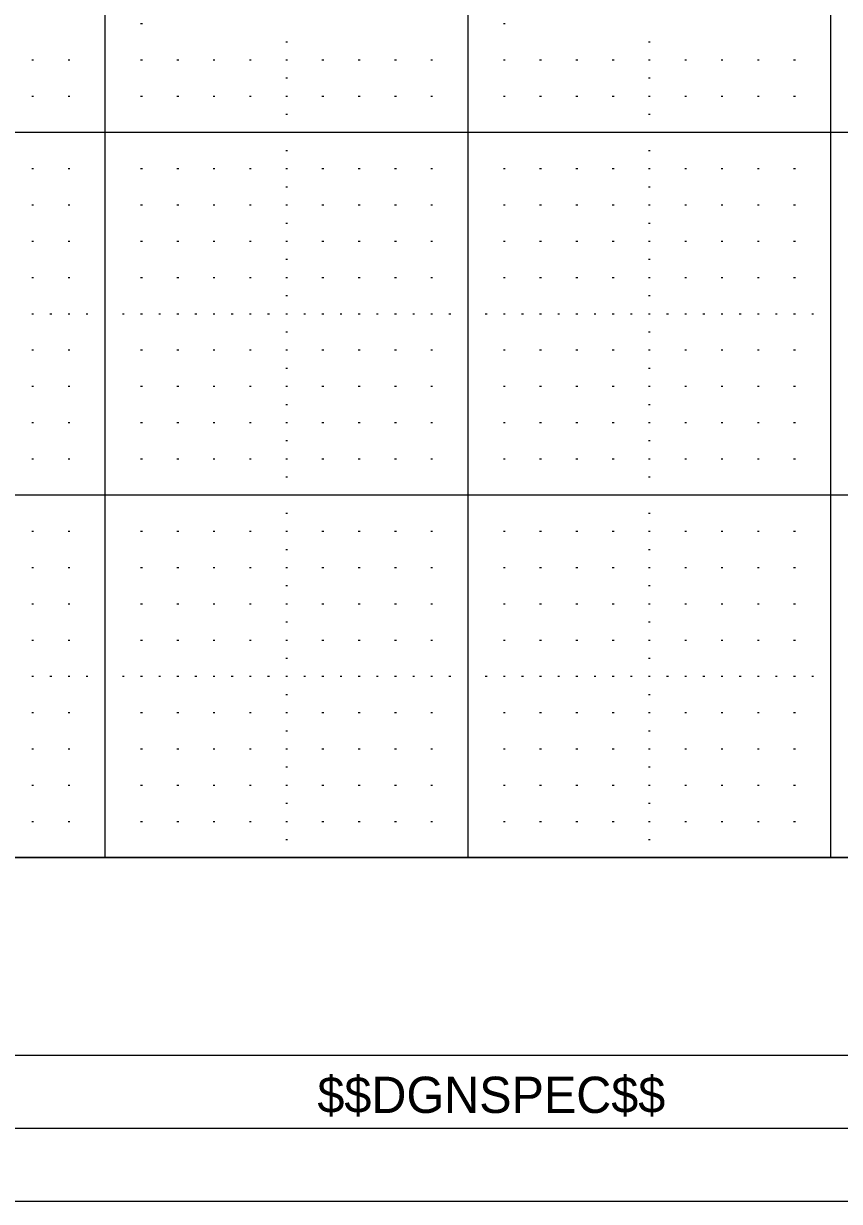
# Model space of a CAD drawing. Extents: x -3.6 to 32.1, y -0.4 to 25.6.
# Drawn here: x 27.583 to 29.832, y -0.403 to 2.845 of the extents above; entities that cross this region are included whole.
import ezdxf

# ---------------------------------------------------------------- set-up
doc = ezdxf.new("R2010")
doc.units = 0
for name, color, linetype in [('Level 4', 7, 'Continuous'), ('Level 48', 7, 'Continuous'), ('Level 5', 7, 'Continuous'), ('Level 62', 7, 'Continuous'), ('Level 63', 7, 'Continuous'), ('Level 63 Full', 7, 'Continuous'), ('R_Border Prem', 7, 'Continuous')]:
    doc.layers.add(name, color=color, linetype=linetype)

msp = doc.modelspace()

# ---------------------------------------------------------------- linework, layer by layer
at = {"layer": 'Level 4'}
for p, q in [((27.808, 0.545), (27.808, 19.545)), ((28.808, 0.545), (28.808, 19.545)), ((29.808, 0.545), (29.808, 19.545)), ((31.617, 2.545), (-0.001, 2.545)), ((31.617, 1.545), (-0.001, 1.545)), ((31.617, 0.545), (-0.001, 0.545))]:
    msp.add_line(p, q, dxfattribs=at)
at = {"layer": 'Level 5'}
for p, q in [((27.9055, 2.845), (27.9105, 2.845)), ((28.9055, 2.845), (28.9105, 2.845)), ((28.3055, 2.795), (28.3105, 2.795)), ((29.3055, 2.795), (29.3105, 2.795)), ((27.6055, 2.745), (27.6105, 2.745)), ((27.7055, 2.745), (27.7105, 2.745)), ((27.9055, 2.745), (27.9105, 2.745)), ((28.0055, 2.745), (28.0105, 2.745)), ((28.1055, 2.745), (28.1105, 2.745)), ((28.2055, 2.745), (28.2105, 2.745)), ((28.3055, 2.745), (28.3105, 2.745)), ((28.4055, 2.745), (28.4105, 2.745)), ((28.5055, 2.745), (28.5105, 2.745)), ((28.6055, 2.745), (28.6105, 2.745)), ((28.7055, 2.745), (28.7105, 2.745)), ((28.9055, 2.745), (28.9105, 2.745)), ((29.0055, 2.745), (29.0105, 2.745)), ((29.1055, 2.745), (29.1105, 2.745)), ((29.2055, 2.745), (29.2105, 2.745)), ((29.3055, 2.745), (29.3105, 2.745)), ((29.4055, 2.745), (29.4105, 2.745)), ((29.5055, 2.745), (29.5105, 2.745)), ((29.6055, 2.745), (29.6105, 2.745)), ((29.7055, 2.745), (29.7105, 2.745)), ((28.3055, 2.695), (28.3105, 2.695)), ((29.3055, 2.695), (29.3105, 2.695)), ((27.6055, 2.645), (27.6105, 2.645)), ((27.7055, 2.645), (27.7105, 2.645)), ((27.9055, 2.645), (27.9105, 2.645)), ((28.0055, 2.645), (28.0105, 2.645)), ((28.1055, 2.645), (28.1105, 2.645)), ((28.2055, 2.645), (28.2105, 2.645)), ((28.3055, 2.645), (28.3105, 2.645)), ((28.4055, 2.645), (28.4105, 2.645)), ((28.5055, 2.645), (28.5105, 2.645)), ((28.6055, 2.645), (28.6105, 2.645)), ((28.7055, 2.645), (28.7105, 2.645)), ((28.9055, 2.645), (28.9105, 2.645)), ((29.0055, 2.645), (29.0105, 2.645)), ((29.1055, 2.645), (29.1105, 2.645)), ((29.2055, 2.645), (29.2105, 2.645)), ((29.3055, 2.645), (29.3105, 2.645)), ((29.4055, 2.645), (29.4105, 2.645)), ((29.5055, 2.645), (29.5105, 2.645)), ((29.6055, 2.645), (29.6105, 2.645)), ((29.7055, 2.645), (29.7105, 2.645)), ((28.3055, 2.595), (28.3105, 2.595)), ((29.3055, 2.595), (29.3105, 2.595)), ((28.3055, 2.495), (28.3105, 2.495)), ((29.3055, 2.495), (29.3105, 2.495)), ((27.6055, 2.445), (27.6105, 2.445)), ((27.7055, 2.445), (27.7105, 2.445)), ((27.9055, 2.445), (27.9105, 2.445)), ((28.0055, 2.445), (28.0105, 2.445)), ((28.1055, 2.445), (28.1105, 2.445)), ((28.2055, 2.445), (28.2105, 2.445)), ((28.3055, 2.445), (28.3105, 2.445)), ((28.4055, 2.445), (28.4105, 2.445)), ((28.5055, 2.445), (28.5105, 2.445)), ((28.6055, 2.445), (28.6105, 2.445)), ((28.7055, 2.445), (28.7105, 2.445)), ((28.9055, 2.445), (28.9105, 2.445)), ((29.0055, 2.445), (29.0105, 2.445)), ((29.1055, 2.445), (29.1105, 2.445)), ((29.2055, 2.445), (29.2105, 2.445)), ((29.3055, 2.445), (29.3105, 2.445)), ((29.4055, 2.445), (29.4105, 2.445)), ((29.5055, 2.445), (29.5105, 2.445)), ((29.6055, 2.445), (29.6105, 2.445)), ((29.7055, 2.445), (29.7105, 2.445)), ((28.3055, 2.395), (28.3105, 2.395)), ((29.3055, 2.395), (29.3105, 2.395)), ((27.6055, 2.345), (27.6105, 2.345)), ((27.7055, 2.345), (27.7105, 2.345)), ((27.9055, 2.345), (27.9105, 2.345)), ((28.0055, 2.345), (28.0105, 2.345)), ((28.1055, 2.345), (28.1105, 2.345)), ((28.2055, 2.345), (28.2105, 2.345)), ((28.3055, 2.345), (28.3105, 2.345)), ((28.4055, 2.345), (28.4105, 2.345)), ((28.5055, 2.345), (28.5105, 2.345)), ((28.6055, 2.345), (28.6105, 2.345)), ((28.7055, 2.345), (28.7105, 2.345)), ((28.9055, 2.345), (28.9105, 2.345)), ((29.0055, 2.345), (29.0105, 2.345)), ((29.1055, 2.345), (29.1105, 2.345)), ((29.2055, 2.345), (29.2105, 2.345)), ((29.3055, 2.345), (29.3105, 2.345)), ((29.4055, 2.345), (29.4105, 2.345)), ((29.5055, 2.345), (29.5105, 2.345)), ((29.6055, 2.345), (29.6105, 2.345)), ((29.7055, 2.345), (29.7105, 2.345)), ((28.3055, 2.295), (28.3105, 2.295)), ((29.3055, 2.295), (29.3105, 2.295)), ((27.6055, 2.245), (27.6105, 2.245)), ((27.7055, 2.245), (27.7105, 2.245)), ((27.9055, 2.245), (27.9105, 2.245)), ((28.0055, 2.245), (28.0105, 2.245)), ((28.1055, 2.245), (28.1105, 2.245)), ((28.2055, 2.245), (28.2105, 2.245)), ((28.3055, 2.245), (28.3105, 2.245)), ((28.4055, 2.245), (28.4105, 2.245)), ((28.5055, 2.245), (28.5105, 2.245)), ((28.6055, 2.245), (28.6105, 2.245)), ((28.7055, 2.245), (28.7105, 2.245)), ((28.9055, 2.245), (28.9105, 2.245)), ((29.0055, 2.245), (29.0105, 2.245)), ((29.1055, 2.245), (29.1105, 2.245)), ((29.2055, 2.245), (29.2105, 2.245)), ((29.3055, 2.245), (29.3105, 2.245)), ((29.4055, 2.245), (29.4105, 2.245)), ((29.5055, 2.245), (29.5105, 2.245)), ((29.6055, 2.245), (29.6105, 2.245)), ((29.7055, 2.245), (29.7105, 2.245)), ((28.3055, 2.195), (28.3105, 2.195)), ((29.3055, 2.195), (29.3105, 2.195)), ((27.6055, 2.145), (27.6105, 2.145)), ((27.7055, 2.145), (27.7105, 2.145)), ((27.9055, 2.145), (27.9105, 2.145)), ((28.0055, 2.145), (28.0105, 2.145)), ((28.1055, 2.145), (28.1105, 2.145)), ((28.2055, 2.145), (28.2105, 2.145)), ((28.3055, 2.145), (28.3105, 2.145)), ((28.4055, 2.145), (28.4105, 2.145)), ((28.5055, 2.145), (28.5105, 2.145)), ((28.6055, 2.145), (28.6105, 2.145)), ((28.7055, 2.145), (28.7105, 2.145)), ((28.9055, 2.145), (28.9105, 2.145)), ((29.0055, 2.145), (29.0105, 2.145)), ((29.1055, 2.145), (29.1105, 2.145)), ((29.2055, 2.145), (29.2105, 2.145)), ((29.3055, 2.145), (29.3105, 2.145)), ((29.4055, 2.145), (29.4105, 2.145)), ((29.5055, 2.145), (29.5105, 2.145)), ((29.6055, 2.145), (29.6105, 2.145)), ((29.7055, 2.145), (29.7105, 2.145)), ((28.3055, 2.095), (28.3105, 2.095)), ((29.3055, 2.095), (29.3105, 2.095)), ((27.6055, 2.045), (27.6105, 2.045)), ((27.6555, 2.045), (27.6605, 2.045)), ((27.7055, 2.045), (27.7105, 2.045)), ((27.7555, 2.045), (27.7605, 2.045)), ((27.8555, 2.045), (27.8605, 2.045)), ((27.9055, 2.045), (27.9105, 2.045)), ((27.9555, 2.045), (27.9605, 2.045)), ((28.0055, 2.045), (28.0105, 2.045)), ((28.0555, 2.045), (28.0605, 2.045)), ((28.1055, 2.045), (28.1105, 2.045)), ((28.1555, 2.045), (28.1605, 2.045)), ((28.2055, 2.045), (28.2105, 2.045)), ((28.2555, 2.045), (28.2605, 2.045)), ((28.3055, 2.045), (28.3105, 2.045)), ((28.3555, 2.045), (28.3605, 2.045)), ((28.4055, 2.045), (28.4105, 2.045)), ((28.4555, 2.045), (28.4605, 2.045)), ((28.5055, 2.045), (28.5105, 2.045)), ((28.5555, 2.045), (28.5605, 2.045)), ((28.6055, 2.045), (28.6105, 2.045)), ((28.6555, 2.045), (28.6605, 2.045)), ((28.7055, 2.045), (28.7105, 2.045)), ((28.7555, 2.045), (28.7605, 2.045)), ((28.8555, 2.045), (28.8605, 2.045)), ((28.9055, 2.045), (28.9105, 2.045)), ((28.9555, 2.045), (28.9605, 2.045)), ((29.0055, 2.045), (29.0105, 2.045)), ((29.0555, 2.045), (29.0605, 2.045)), ((29.1055, 2.045), (29.1105, 2.045)), ((29.1555, 2.045), (29.1605, 2.045)), ((29.2055, 2.045), (29.2105, 2.045)), ((29.2555, 2.045), (29.2605, 2.045)), ((29.3055, 2.045), (29.3105, 2.045)), ((29.3555, 2.045), (29.3605, 2.045)), ((29.4055, 2.045), (29.4105, 2.045)), ((29.4555, 2.045), (29.4605, 2.045)), ((29.5055, 2.045), (29.5105, 2.045)), ((29.5555, 2.045), (29.5605, 2.045)), ((29.6055, 2.045), (29.6105, 2.045)), ((29.6555, 2.045), (29.6605, 2.045)), ((29.7055, 2.045), (29.7105, 2.045)), ((29.7555, 2.045), (29.7605, 2.045)), ((28.3055, 1.995), (28.3105, 1.995)), ((29.3055, 1.995), (29.3105, 1.995)), ((27.6055, 1.945), (27.6105, 1.945)), ((27.7055, 1.945), (27.7105, 1.945)), ((27.9055, 1.945), (27.9105, 1.945)), ((28.0055, 1.945), (28.0105, 1.945)), ((28.1055, 1.945), (28.1105, 1.945)), ((28.2055, 1.945), (28.2105, 1.945)), ((28.3055, 1.945), (28.3105, 1.945)), ((28.4055, 1.945), (28.4105, 1.945)), ((28.5055, 1.945), (28.5105, 1.945)), ((28.6055, 1.945), (28.6105, 1.945)), ((28.7055, 1.945), (28.7105, 1.945)), ((28.9055, 1.945), (28.9105, 1.945)), ((29.0055, 1.945), (29.0105, 1.945)), ((29.1055, 1.945), (29.1105, 1.945)), ((29.2055, 1.945), (29.2105, 1.945)), ((29.3055, 1.945), (29.3105, 1.945)), ((29.4055, 1.945), (29.4105, 1.945)), ((29.5055, 1.945), (29.5105, 1.945)), ((29.6055, 1.945), (29.6105, 1.945)), ((29.7055, 1.945), (29.7105, 1.945)), ((28.3055, 1.895), (28.3105, 1.895)), ((29.3055, 1.895), (29.3105, 1.895)), ((27.6055, 1.845), (27.6105, 1.845)), ((27.7055, 1.845), (27.7105, 1.845)), ((27.9055, 1.845), (27.9105, 1.845)), ((28.0055, 1.845), (28.0105, 1.845)), ((28.1055, 1.845), (28.1105, 1.845)), ((28.2055, 1.845), (28.2105, 1.845)), ((28.3055, 1.845), (28.3105, 1.845)), ((28.4055, 1.845), (28.4105, 1.845)), ((28.5055, 1.845), (28.5105, 1.845)), ((28.6055, 1.845), (28.6105, 1.845)), ((28.7055, 1.845), (28.7105, 1.845)), ((28.9055, 1.845), (28.9105, 1.845)), ((29.0055, 1.845), (29.0105, 1.845)), ((29.1055, 1.845), (29.1105, 1.845)), ((29.2055, 1.845), (29.2105, 1.845)), ((29.3055, 1.845), (29.3105, 1.845)), ((29.4055, 1.845), (29.4105, 1.845)), ((29.5055, 1.845), (29.5105, 1.845)), ((29.6055, 1.845), (29.6105, 1.845)), ((29.7055, 1.845), (29.7105, 1.845)), ((28.3055, 1.795), (28.3105, 1.795)), ((29.3055, 1.795), (29.3105, 1.795)), ((27.6055, 1.745), (27.6105, 1.745)), ((27.7055, 1.745), (27.7105, 1.745)), ((27.9055, 1.745), (27.9105, 1.745)), ((28.0055, 1.745), (28.0105, 1.745)), ((28.1055, 1.745), (28.1105, 1.745)), ((28.2055, 1.745), (28.2105, 1.745)), ((28.3055, 1.745), (28.3105, 1.745)), ((28.4055, 1.745), (28.4105, 1.745)), ((28.5055, 1.745), (28.5105, 1.745)), ((28.6055, 1.745), (28.6105, 1.745)), ((28.7055, 1.745), (28.7105, 1.745)), ((28.9055, 1.745), (28.9105, 1.745)), ((29.0055, 1.745), (29.0105, 1.745)), ((29.1055, 1.745), (29.1105, 1.745)), ((29.2055, 1.745), (29.2105, 1.745)), ((29.3055, 1.745), (29.3105, 1.745)), ((29.4055, 1.745), (29.4105, 1.745)), ((29.5055, 1.745), (29.5105, 1.745)), ((29.6055, 1.745), (29.6105, 1.745)), ((29.7055, 1.745), (29.7105, 1.745)), ((28.3055, 1.695), (28.3105, 1.695)), ((29.3055, 1.695), (29.3105, 1.695)), ((27.6055, 1.645), (27.6105, 1.645)), ((27.7055, 1.645), (27.7105, 1.645)), ((27.9055, 1.645), (27.9105, 1.645)), ((28.0055, 1.645), (28.0105, 1.645)), ((28.1055, 1.645), (28.1105, 1.645)), ((28.2055, 1.645), (28.2105, 1.645)), ((28.3055, 1.645), (28.3105, 1.645)), ((28.4055, 1.645), (28.4105, 1.645)), ((28.5055, 1.645), (28.5105, 1.645)), ((28.6055, 1.645), (28.6105, 1.645)), ((28.7055, 1.645), (28.7105, 1.645)), ((28.9055, 1.645), (28.9105, 1.645)), ((29.0055, 1.645), (29.0105, 1.645)), ((29.1055, 1.645), (29.1105, 1.645)), ((29.2055, 1.645), (29.2105, 1.645)), ((29.3055, 1.645), (29.3105, 1.645)), ((29.4055, 1.645), (29.4105, 1.645)), ((29.5055, 1.645), (29.5105, 1.645)), ((29.6055, 1.645), (29.6105, 1.645)), ((29.7055, 1.645), (29.7105, 1.645)), ((28.3055, 1.595), (28.3105, 1.595)), ((29.3055, 1.595), (29.3105, 1.595)), ((28.3055, 1.495), (28.3105, 1.495)), ((29.3055, 1.495), (29.3105, 1.495)), ((27.6055, 1.445), (27.6105, 1.445)), ((27.7055, 1.445), (27.7105, 1.445)), ((27.9055, 1.445), (27.9105, 1.445)), ((28.0055, 1.445), (28.0105, 1.445)), ((28.1055, 1.445), (28.1105, 1.445)), ((28.2055, 1.445), (28.2105, 1.445)), ((28.3055, 1.445), (28.3105, 1.445)), ((28.4055, 1.445), (28.4105, 1.445)), ((28.5055, 1.445), (28.5105, 1.445)), ((28.6055, 1.445), (28.6105, 1.445)), ((28.7055, 1.445), (28.7105, 1.445)), ((28.9055, 1.445), (28.9105, 1.445)), ((29.0055, 1.445), (29.0105, 1.445)), ((29.1055, 1.445), (29.1105, 1.445)), ((29.2055, 1.445), (29.2105, 1.445)), ((29.3055, 1.445), (29.3105, 1.445)), ((29.4055, 1.445), (29.4105, 1.445)), ((29.5055, 1.445), (29.5105, 1.445)), ((29.6055, 1.445), (29.6105, 1.445)), ((29.7055, 1.445), (29.7105, 1.445)), ((28.3055, 1.395), (28.3105, 1.395)), ((29.3055, 1.395), (29.3105, 1.395)), ((27.6055, 1.345), (27.6105, 1.345)), ((27.7055, 1.345), (27.7105, 1.345)), ((27.9055, 1.345), (27.9105, 1.345)), ((28.0055, 1.345), (28.0105, 1.345)), ((28.1055, 1.345), (28.1105, 1.345)), ((28.2055, 1.345), (28.2105, 1.345)), ((28.3055, 1.345), (28.3105, 1.345)), ((28.4055, 1.345), (28.4105, 1.345)), ((28.5055, 1.345), (28.5105, 1.345)), ((28.6055, 1.345), (28.6105, 1.345)), ((28.7055, 1.345), (28.7105, 1.345)), ((28.9055, 1.345), (28.9105, 1.345)), ((29.0055, 1.345), (29.0105, 1.345)), ((29.1055, 1.345), (29.1105, 1.345)), ((29.2055, 1.345), (29.2105, 1.345)), ((29.3055, 1.345), (29.3105, 1.345)), ((29.4055, 1.345), (29.4105, 1.345)), ((29.5055, 1.345), (29.5105, 1.345)), ((29.6055, 1.345), (29.6105, 1.345)), ((29.7055, 1.345), (29.7105, 1.345)), ((28.3055, 1.295), (28.3105, 1.295)), ((29.3055, 1.295), (29.3105, 1.295)), ((27.6055, 1.245), (27.6105, 1.245)), ((27.7055, 1.245), (27.7105, 1.245)), ((27.9055, 1.245), (27.9105, 1.245)), ((28.0055, 1.245), (28.0105, 1.245)), ((28.1055, 1.245), (28.1105, 1.245)), ((28.2055, 1.245), (28.2105, 1.245)), ((28.3055, 1.245), (28.3105, 1.245)), ((28.4055, 1.245), (28.4105, 1.245)), ((28.5055, 1.245), (28.5105, 1.245)), ((28.6055, 1.245), (28.6105, 1.245)), ((28.7055, 1.245), (28.7105, 1.245)), ((28.9055, 1.245), (28.9105, 1.245)), ((29.0055, 1.245), (29.0105, 1.245)), ((29.1055, 1.245), (29.1105, 1.245)), ((29.2055, 1.245), (29.2105, 1.245)), ((29.3055, 1.245), (29.3105, 1.245)), ((29.4055, 1.245), (29.4105, 1.245)), ((29.5055, 1.245), (29.5105, 1.245)), ((29.6055, 1.245), (29.6105, 1.245)), ((29.7055, 1.245), (29.7105, 1.245)), ((28.3055, 1.195), (28.3105, 1.195)), ((29.3055, 1.195), (29.3105, 1.195)), ((27.6055, 1.145), (27.6105, 1.145)), ((27.7055, 1.145), (27.7105, 1.145)), ((27.9055, 1.145), (27.9105, 1.145)), ((28.0055, 1.145), (28.0105, 1.145)), ((28.1055, 1.145), (28.1105, 1.145)), ((28.2055, 1.145), (28.2105, 1.145)), ((28.3055, 1.145), (28.3105, 1.145)), ((28.4055, 1.145), (28.4105, 1.145)), ((28.5055, 1.145), (28.5105, 1.145)), ((28.6055, 1.145), (28.6105, 1.145)), ((28.7055, 1.145), (28.7105, 1.145)), ((28.9055, 1.145), (28.9105, 1.145)), ((29.0055, 1.145), (29.0105, 1.145)), ((29.1055, 1.145), (29.1105, 1.145)), ((29.2055, 1.145), (29.2105, 1.145)), ((29.3055, 1.145), (29.3105, 1.145)), ((29.4055, 1.145), (29.4105, 1.145)), ((29.5055, 1.145), (29.5105, 1.145)), ((29.6055, 1.145), (29.6105, 1.145)), ((29.7055, 1.145), (29.7105, 1.145)), ((28.3055, 1.095), (28.3105, 1.095)), ((29.3055, 1.095), (29.3105, 1.095)), ((27.6055, 1.045), (27.6105, 1.045)), ((27.6555, 1.045), (27.6605, 1.045)), ((27.7055, 1.045), (27.7105, 1.045)), ((27.7555, 1.045), (27.7605, 1.045)), ((27.8555, 1.045), (27.8605, 1.045)), ((27.9055, 1.045), (27.9105, 1.045)), ((27.9555, 1.045), (27.9605, 1.045)), ((28.0055, 1.045), (28.0105, 1.045)), ((28.0555, 1.045), (28.0605, 1.045)), ((28.1055, 1.045), (28.1105, 1.045)), ((28.1555, 1.045), (28.1605, 1.045)), ((28.2055, 1.045), (28.2105, 1.045)), ((28.2555, 1.045), (28.2605, 1.045)), ((28.3055, 1.045), (28.3105, 1.045)), ((28.3555, 1.045), (28.3605, 1.045)), ((28.4055, 1.045), (28.4105, 1.045)), ((28.4555, 1.045), (28.4605, 1.045)), ((28.5055, 1.045), (28.5105, 1.045)), ((28.5555, 1.045), (28.5605, 1.045)), ((28.6055, 1.045), (28.6105, 1.045)), ((28.6555, 1.045), (28.6605, 1.045)), ((28.7055, 1.045), (28.7105, 1.045)), ((28.7555, 1.045), (28.7605, 1.045)), ((28.8555, 1.045), (28.8605, 1.045)), ((28.9055, 1.045), (28.9105, 1.045)), ((28.9555, 1.045), (28.9605, 1.045)), ((29.0055, 1.045), (29.0105, 1.045)), ((29.0555, 1.045), (29.0605, 1.045)), ((29.1055, 1.045), (29.1105, 1.045)), ((29.1555, 1.045), (29.1605, 1.045)), ((29.2055, 1.045), (29.2105, 1.045)), ((29.2555, 1.045), (29.2605, 1.045)), ((29.3055, 1.045), (29.3105, 1.045)), ((29.3555, 1.045), (29.3605, 1.045)), ((29.4055, 1.045), (29.4105, 1.045)), ((29.4555, 1.045), (29.4605, 1.045)), ((29.5055, 1.045), (29.5105, 1.045)), ((29.5555, 1.045), (29.5605, 1.045)), ((29.6055, 1.045), (29.6105, 1.045)), ((29.6555, 1.045), (29.6605, 1.045)), ((29.7055, 1.045), (29.7105, 1.045)), ((29.7555, 1.045), (29.7605, 1.045)), ((28.3055, 0.995), (28.3105, 0.995)), ((29.3055, 0.995), (29.3105, 0.995)), ((27.6055, 0.945), (27.6105, 0.945)), ((27.7055, 0.945), (27.7105, 0.945)), ((27.9055, 0.945), (27.9105, 0.945)), ((28.0055, 0.945), (28.0105, 0.945)), ((28.1055, 0.945), (28.1105, 0.945)), ((28.2055, 0.945), (28.2105, 0.945)), ((28.3055, 0.945), (28.3105, 0.945)), ((28.4055, 0.945), (28.4105, 0.945)), ((28.5055, 0.945), (28.5105, 0.945)), ((28.6055, 0.945), (28.6105, 0.945)), ((28.7055, 0.945), (28.7105, 0.945)), ((28.9055, 0.945), (28.9105, 0.945)), ((29.0055, 0.945), (29.0105, 0.945)), ((29.1055, 0.945), (29.1105, 0.945)), ((29.2055, 0.945), (29.2105, 0.945)), ((29.3055, 0.945), (29.3105, 0.945)), ((29.4055, 0.945), (29.4105, 0.945)), ((29.5055, 0.945), (29.5105, 0.945)), ((29.6055, 0.945), (29.6105, 0.945)), ((29.7055, 0.945), (29.7105, 0.945)), ((28.3055, 0.895), (28.3105, 0.895)), ((29.3055, 0.895), (29.3105, 0.895)), ((27.6055, 0.845), (27.6105, 0.845)), ((27.7055, 0.845), (27.7105, 0.845)), ((27.9055, 0.845), (27.9105, 0.845)), ((28.0055, 0.845), (28.0105, 0.845)), ((28.1055, 0.845), (28.1105, 0.845)), ((28.2055, 0.845), (28.2105, 0.845)), ((28.3055, 0.845), (28.3105, 0.845)), ((28.4055, 0.845), (28.4105, 0.845)), ((28.5055, 0.845), (28.5105, 0.845)), ((28.6055, 0.845), (28.6105, 0.845)), ((28.7055, 0.845), (28.7105, 0.845)), ((28.9055, 0.845), (28.9105, 0.845)), ((29.0055, 0.845), (29.0105, 0.845)), ((29.1055, 0.845), (29.1105, 0.845)), ((29.2055, 0.845), (29.2105, 0.845)), ((29.3055, 0.845), (29.3105, 0.845)), ((29.4055, 0.845), (29.4105, 0.845)), ((29.5055, 0.845), (29.5105, 0.845)), ((29.6055, 0.845), (29.6105, 0.845)), ((29.7055, 0.845), (29.7105, 0.845)), ((28.3055, 0.795), (28.3105, 0.795)), ((29.3055, 0.795), (29.3105, 0.795)), ((27.6055, 0.745), (27.6105, 0.745)), ((27.7055, 0.745), (27.7105, 0.745)), ((27.9055, 0.745), (27.9105, 0.745)), ((28.0055, 0.745), (28.0105, 0.745)), ((28.1055, 0.745), (28.1105, 0.745)), ((28.2055, 0.745), (28.2105, 0.745)), ((28.3055, 0.745), (28.3105, 0.745)), ((28.4055, 0.745), (28.4105, 0.745)), ((28.5055, 0.745), (28.5105, 0.745)), ((28.6055, 0.745), (28.6105, 0.745)), ((28.7055, 0.745), (28.7105, 0.745)), ((28.9055, 0.745), (28.9105, 0.745)), ((29.0055, 0.745), (29.0105, 0.745)), ((29.1055, 0.745), (29.1105, 0.745)), ((29.2055, 0.745), (29.2105, 0.745)), ((29.3055, 0.745), (29.3105, 0.745)), ((29.4055, 0.745), (29.4105, 0.745)), ((29.5055, 0.745), (29.5105, 0.745)), ((29.6055, 0.745), (29.6105, 0.745)), ((29.7055, 0.745), (29.7105, 0.745)), ((28.3055, 0.695), (28.3105, 0.695)), ((29.3055, 0.695), (29.3105, 0.695)), ((27.6055, 0.645), (27.6105, 0.645)), ((27.7055, 0.645), (27.7105, 0.645)), ((27.9055, 0.645), (27.9105, 0.645)), ((28.0055, 0.645), (28.0105, 0.645)), ((28.1055, 0.645), (28.1105, 0.645)), ((28.2055, 0.645), (28.2105, 0.645)), ((28.3055, 0.645), (28.3105, 0.645)), ((28.4055, 0.645), (28.4105, 0.645)), ((28.5055, 0.645), (28.5105, 0.645)), ((28.6055, 0.645), (28.6105, 0.645)), ((28.7055, 0.645), (28.7105, 0.645)), ((28.9055, 0.645), (28.9105, 0.645)), ((29.0055, 0.645), (29.0105, 0.645)), ((29.1055, 0.645), (29.1105, 0.645)), ((29.2055, 0.645), (29.2105, 0.645)), ((29.3055, 0.645), (29.3105, 0.645)), ((29.4055, 0.645), (29.4105, 0.645)), ((29.5055, 0.645), (29.5105, 0.645)), ((29.6055, 0.645), (29.6105, 0.645)), ((29.7055, 0.645), (29.7105, 0.645)), ((28.3055, 0.595), (28.3105, 0.595)), ((29.3055, 0.595), (29.3105, 0.595))]:
    msp.add_line(p, q, dxfattribs=at)
at = {"layer": 'Level 62'}
msp.add_line((0.808, 0.545), (30.808, 0.545), dxfattribs=at)
at = {"layer": 'Level 63'}
msp.add_lwpolyline([(-1.263, -0.2005), (32.067, -0.2005), (32.067, 20.7465), (-1.263, 20.7465)], close=True, dxfattribs=at)
at = {"layer": 'Level 63 Full'}
msp.add_lwpolyline([(32.017, -0.403), (-3.583, -0.403), (-3.583, 20.947), (32.017, 20.947)], close=True, dxfattribs=at)
at = {"layer": 'R_Border Prem'}
msp.add_line((31.617, -0.001), (-0.001, -0.001), dxfattribs=at)

# ---------------------------------------------------------------- texts
at = {"layer": 'Level 48'}
msp.add_text('$$DGNSPEC$$', height=0.100002, dxfattribs=at).set_placement((28.3929, -0.159))

doc.saveas('drawing.dxf')
